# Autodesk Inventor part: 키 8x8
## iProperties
Company: 한국ATC센터
Created: 2014-11
Part Number: 키 8x8
Document SubType Name: Modeling
Designer: KYOUNG IL JANG
Density: 7.86 g/cm^3
Material: 강, 연강
Mass: 10.2483 g
Surface Area: 7.8646 cm^2
Volume: 1.30386 cm^3
Author: KYOUNG IL JANG
